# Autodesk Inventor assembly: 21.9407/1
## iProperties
Created: 2010-10
Part Number: 21.9407/1
Document SubType Name: Assembly
Designer: Administrator
Description: 5" RIGID CASTER
Vendor: V
Translation Standard: STEP AP214IS
FileName: Colson-2.03256.445 BRK5 .step.step
PreProcessor: SolidWorks 2010
PostProcessor: Build: 236a, Release: 2009 RTM - Date: Fri 02/22/2008
Sent Units: Inches
Uncertainty: 1e-05
Author: Administrator
